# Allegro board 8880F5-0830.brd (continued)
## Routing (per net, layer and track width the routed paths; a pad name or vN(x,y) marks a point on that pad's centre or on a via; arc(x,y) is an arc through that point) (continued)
N26504664: length 3
  BOTTOM w0.119: UNK4R25.2 380.15,177.84 380.62,178.31 UNK4K5.6
N26504685: length 3
  BOTTOM w0.119: UNK4R18.1 396.5,161.33 396.03,161.8 UNK4K3.5
N26504686: length 3
  BOTTOM w0.119: UNK4R17.2 393.35,161.33 393.83,161.8 UNK4K3.6
N26504687: length 3
  BOTTOM w0.119: UNK4K3.4 396.03,173.48 396.5,173.95 UNK4R16.1
N26504688: length 3
  BOTTOM w0.119: UNK4K3.3 393.83,173.48 393.35,173.95 UNK4R15.2
N26504691: length 3
  BOTTOM w0.119: UNK4K1.5 344.43,130.77 343.96,130.3 UNK4R10.1
N26504692: length 3
  BOTTOM w0.119: UNK4R9.2 343.96,133.44 344.43,132.97 UNK4K1.6
N26504693: length 3
  BOTTOM w0.119: UNK4R8.1 356.57,130.3 356.1,130.77 UNK4K1.4
N26504694: length 3
  BOTTOM w0.119: UNK4K1.3 356.1,132.97 356.57,133.44 UNK4R7.2
N26504696: length 3
  BOTTOM w0.119: UNK4R11.2 380.15,173.69 380.62,173.22 UNK4K2.3
N26504697: length 3
  BOTTOM w0.119: UNK4K2.4 382.82,173.22 383.29,173.69 UNK4R12.1
N26504698: length 3
  BOTTOM w0.119: UNK4R22.1 409.96,161.33 409.49,161.8 UNK4K4.5
N26504700: length 3
  BOTTOM w0.119: UNK4K4.3 407.29,173.48 406.82,173.95 UNK4R19.2
N26504701: length 3
  BOTTOM w0.119: UNK4R20.1 409.96,173.95 409.49,173.48 UNK4K4.4
N26504702: length 3
  BOTTOM w0.119: UNK4R21.2 406.82,161.33 407.29,161.8 UNK4K4.6
N26504703: length 3
  BOTTOM w0.119: UNK4R14.1 383.29,161.08 382.82,161.55 UNK4K2.5
N26504704: length 3
  BOTTOM w0.119: UNK4K2.6 380.62,161.55 380.15,161.08 UNK4R13.2
N26504896:
  vias: v1(456.25,190.45)
N26504897:
  vias: v1(451.68,190.45)
N26504904:
  vias: v1(302.38,213.82) v1(302.38,212.66) v1(304.65,211.67)
N26504906:
  vias: v1(302.38,215.98) v1(302.38,214.82) v1(304.65,216.97)
N26504907:
  vias: v1(301.21,216.98) v1(302.38,216.98)
N26504908:
  vias: v1(301.21,211.66) v1(302.38,211.66)
N26504937:
  vias: v1(451.62,188.98)
N26505003:
  vias: v1(483.1,197.87)
N26509126:
  vias: v1(491.1,183.24)
N26509130:
  vias: v1(490.86,169.47)
N26509132:
  vias: v1(485.8,169.47)
N26509139:
  vias: v1(477.53,175.15)
N26509173:
  vias: v1(477.43,161.55)
N26509211:
  vias: v1(485.8,183.19)
N26509969:
  vias: v1(511.6,274.32)
N26509975:
  vias: v1(518.37,290.83)
N26509980:
  vias: v1(528.11,274.32)
N26510100:
  vias: v1(478.58,257.81)
N26510106:
  vias: v1(528.11,257.81)
N26510178:
  vias: v1(511.6,257.81)
N26510184:
  vias: v1(495.09,257.81)
N26510317:
  vias: v1(518.37,257.81)
N26510323:
  vias: v1(468.84,257.81)
N26510327:
  vias: v1(485.35,257.81)
N26510329:
  vias: v1(518.37,274.32)
N26510335:
  vias: v1(501.86,274.32)

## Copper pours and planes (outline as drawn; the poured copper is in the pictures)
GND on L02_DGND, L03_SIGNAL, L04_DGND, L05_SIGNAL, L06_DGND, L07_SIGNAL, L08_DGND, L10_DGND, L12_DGND, L14_DGND, L16_DGND, L19_DGND, L21_DGND, L23_DGND, L25_DGND, L27_DGND, L28_SIGNAL, L29_DGND, L30_SIGNAL, L31_DGND: 1.02,1.27 1.02,427.99 205.54,427.99 216.92,422.32 228.3,427.99 352.84,427.99 364.23,422.27 375.62,427.99 580.13,427.99 580.13,1.27 301.95,1.27 290.57,6.93 279.19,1.27
(no net) on L32_SIGNAL, L33_DGND: 1.02,1.27 1.02,427.99 205.54,427.99 216.92,422.32 228.3,427.99 352.84,427.99 364.23,422.27 375.62,427.99 580.13,427.99 580.13,1.27 301.95,1.27 290.57,6.93 279.19,1.27

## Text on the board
User.Comments: CR_SS_6 | CR_2_2 | CR_RELAY_19 | CR_4_2 | CR_3_1 | CR_2_3 | CR_UNNAMED_2 | CR_UNNAMED_3 | CR_QQ_28 | CR_A_23 | CR_5_1 | CR_5_2 | CR_QQ_12 | CR_QQ_11 | CR_A_28 | CR_A_21 | CR_A_25 | CR_A_26 | CR_A_30 | CR_A_32 | CR_A_22 | CR_A_24 | CR_A_27 | CR_A_29 | CR_A_31 | CR_A_20
